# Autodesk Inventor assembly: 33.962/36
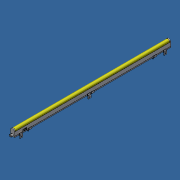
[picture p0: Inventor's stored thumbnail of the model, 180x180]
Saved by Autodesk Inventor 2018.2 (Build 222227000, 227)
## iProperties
Created: 2018-05
Part Number: 33.962/36
Document SubType Name: Assembly
Designer: amoles
Description: LED STRIP LIGHT 3FT
Author: amoles
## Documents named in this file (6)
- Y:\INVENTOR LIBRARIES\PARTS LIBRARY\WORKSTATION\LIGHTS OUTWATER PLASTICS\33.9620_36 LED STRIP LIGHT 3FT.iam
- Y:\INVENTOR LIBRARIES\PARTS LIBRARY\WORKSTATION\LIGHTS OUTWATER PLASTICS\SUBCOMPONENTS\33.9620 PLASTIC MOUNTING CLIP IN LINE.ipt
- Y:\INVENTOR LIBRARIES\PARTS LIBRARY\WORKSTATION\LIGHTS OUTWATER PLASTICS\SUBCOMPONENTS\33.9620 PLASTIC MOUNTING CLIP OFFSET.ipt
- Y:\INVENTOR LIBRARIES\PARTS LIBRARY\WORKSTATION\LIGHTS OUTWATER PLASTICS\SUBCOMPONENTS\33.9620 RECEPTACLE COVER.ipt
- Y:\INVENTOR LIBRARIES\PARTS LIBRARY\WORKSTATION\LIGHTS OUTWATER PLASTICS\SUBCOMPONENTS\33.9620 M3.9 MOUNTING SCREW.ipt
- Y:\INVENTOR LIBRARIES\PARTS LIBRARY\WORKSTATION\LIGHTS OUTWATER PLASTICS\SUBCOMPONENTS\33.9620_36 LED STRIP LIGHT 3FT.ipt
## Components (11 placed, 5 different names)
1. 33.9620_36 LED STRIP LIGHT 3FT:1 — Mate:1, Flush:1, Flush:4, Flush:6, Flush:10, Flush:11, Mate:2, Flush:12, Flush:13, Mate:3, Angle:1, Mate:4, Mate:5, Mate:7, Mate:8
2. 33.9620 PLASTIC MOUNTING CLIP IN LINE:1 — Mate:1, Flush:1, Flush:2, Flush:3, Flush:4, Flush:5, Flush:7, Insert:2
3. 33.9620 PLASTIC MOUNTING CLIP IN LINE:2 — Flush:2, Flush:3, Flush:8, Flush:9, Flush:12, Insert:1
4. 33.9620 PLASTIC MOUNTING CLIP OFFSET:1 — Flush:5, Flush:6, Flush:7
5. 33.9620 PLASTIC MOUNTING CLIP OFFSET:2 — Flush:8, Flush:9, Flush:10
6. 33.9620 RECEPTACLE COVER:1 — Mate:3, Angle:1, Mate:4
7. 33.9620 M3.9 MOUNTING SCREW:1 — Insert:2
8. 33.9620 M3.9 MOUNTING SCREW:2 — Insert:1
9. 33.9620 PLASTIC MOUNTING CLIP IN LINE:3 — Mate:5, Mate:7, Mate:8, Insert:3, Flush:14, Flush:15
10. 33.9620 M3.9 MOUNTING SCREW:3 — Insert:3
11. 33.9620 PLASTIC MOUNTING CLIP OFFSET:3 — Flush:14, Flush:15
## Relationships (26: Flush 15, Mate 7, Insert 3, Angle 1)
- Mate:1: 33.9620_36 LED STRIP LIGHT 3FT:1 ↔ 33.9620 PLASTIC MOUNTING CLIP IN LINE:1
- Flush:1: 33.9620_36 LED STRIP LIGHT 3FT:1 ↔ 33.9620 PLASTIC MOUNTING CLIP IN LINE:1
- Flush:2: 33.9620 PLASTIC MOUNTING CLIP IN LINE:1 ↔ 33.9620 PLASTIC MOUNTING CLIP IN LINE:2
- Flush:3: 33.9620 PLASTIC MOUNTING CLIP IN LINE:1 ↔ 33.9620 PLASTIC MOUNTING CLIP IN LINE:2
- Flush:4: 33.9620_36 LED STRIP LIGHT 3FT:1 ↔ 33.9620 PLASTIC MOUNTING CLIP IN LINE:1
- Flush:5: 33.9620 PLASTIC MOUNTING CLIP IN LINE:1 ↔ 33.9620 PLASTIC MOUNTING CLIP OFFSET:1
- Flush:6: 33.9620_36 LED STRIP LIGHT 3FT:1 ↔ 33.9620 PLASTIC MOUNTING CLIP OFFSET:1
- Flush:7: 33.9620 PLASTIC MOUNTING CLIP IN LINE:1 ↔ 33.9620 PLASTIC MOUNTING CLIP OFFSET:1
- Flush:8: 33.9620 PLASTIC MOUNTING CLIP IN LINE:2 ↔ 33.9620 PLASTIC MOUNTING CLIP OFFSET:2
- Flush:9: 33.9620 PLASTIC MOUNTING CLIP IN LINE:2 ↔ 33.9620 PLASTIC MOUNTING CLIP OFFSET:2
- Flush:10: 33.9620_36 LED STRIP LIGHT 3FT:1 ↔ 33.9620 PLASTIC MOUNTING CLIP OFFSET:2
- Flush:11: 33.9620_36 LED STRIP LIGHT 3FT:1
- Mate:2: 33.9620_36 LED STRIP LIGHT 3FT:1
- Flush:12: 33.9620_36 LED STRIP LIGHT 3FT:1 ↔ 33.9620 PLASTIC MOUNTING CLIP IN LINE:2
- Flush:13: 33.9620_36 LED STRIP LIGHT 3FT:1
- Mate:3: 33.9620_36 LED STRIP LIGHT 3FT:1 ↔ 33.9620 RECEPTACLE COVER:1
- Angle:1: 33.9620_36 LED STRIP LIGHT 3FT:1 ↔ 33.9620 RECEPTACLE COVER:1
- Mate:4: 33.9620_36 LED STRIP LIGHT 3FT:1 ↔ 33.9620 RECEPTACLE COVER:1
- Insert:1: 33.9620 PLASTIC MOUNTING CLIP IN LINE:2 ↔ 33.9620 M3.9 MOUNTING SCREW:2
- Insert:2: 33.9620 PLASTIC MOUNTING CLIP IN LINE:1 ↔ 33.9620 M3.9 MOUNTING SCREW:1
- Mate:5: 33.9620_36 LED STRIP LIGHT 3FT:1 ↔ 33.9620 PLASTIC MOUNTING CLIP IN LINE:3
- Mate:7: 33.9620_36 LED STRIP LIGHT 3FT:1 ↔ 33.9620 PLASTIC MOUNTING CLIP IN LINE:3
- Mate:8: 33.9620_36 LED STRIP LIGHT 3FT:1 ↔ 33.9620 PLASTIC MOUNTING CLIP IN LINE:3
- Insert:3: 33.9620 PLASTIC MOUNTING CLIP IN LINE:3 ↔ 33.9620 M3.9 MOUNTING SCREW:3
- Flush:14: 33.9620 PLASTIC MOUNTING CLIP IN LINE:3 ↔ 33.9620 PLASTIC MOUNTING CLIP OFFSET:3
- Flush:15: 33.9620 PLASTIC MOUNTING CLIP IN LINE:3 ↔ 33.9620 PLASTIC MOUNTING CLIP OFFSET:3
